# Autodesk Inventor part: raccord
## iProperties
Created: 2002-03
Part Number: raccord
Material: Par défaut
Document SubType Name: Modélisation
Designer: User
Control State: 0
Master: False
Checked Out: False
Shininess: 20.0
Length Units: 11269
Angle Units: 11279
Time Units: 11290
Mass Units: 11283
Length Display Precision: 3
Angle Display Precision: 2
Density: 0.0
Volumn: 0.0
Area: 0.0
PropertySet Name: Model Information
Author: User
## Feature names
1. Révolution1 [Revolution]
2. Chanfrein1 [Chamfer]
3. Extrusion1
4. Congé1 [Fillet]
5. Extrusion2
6. Chanfrein2 [Chamfer]
7. Perçage1 [Hole]
8. Perçage2 [Hole]
9. Chanfrein3 [Chamfer]
10. Perçage3 [Hole]
11. Perçage4 [Hole]
12. Perçage5 [Hole]
